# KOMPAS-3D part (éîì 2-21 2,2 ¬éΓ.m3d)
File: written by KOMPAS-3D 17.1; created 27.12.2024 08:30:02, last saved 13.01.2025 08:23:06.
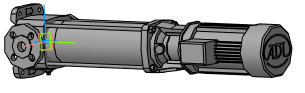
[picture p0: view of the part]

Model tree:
1. Операция без истории:4  (labels: ВМН 2-21 2,2 кВт)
